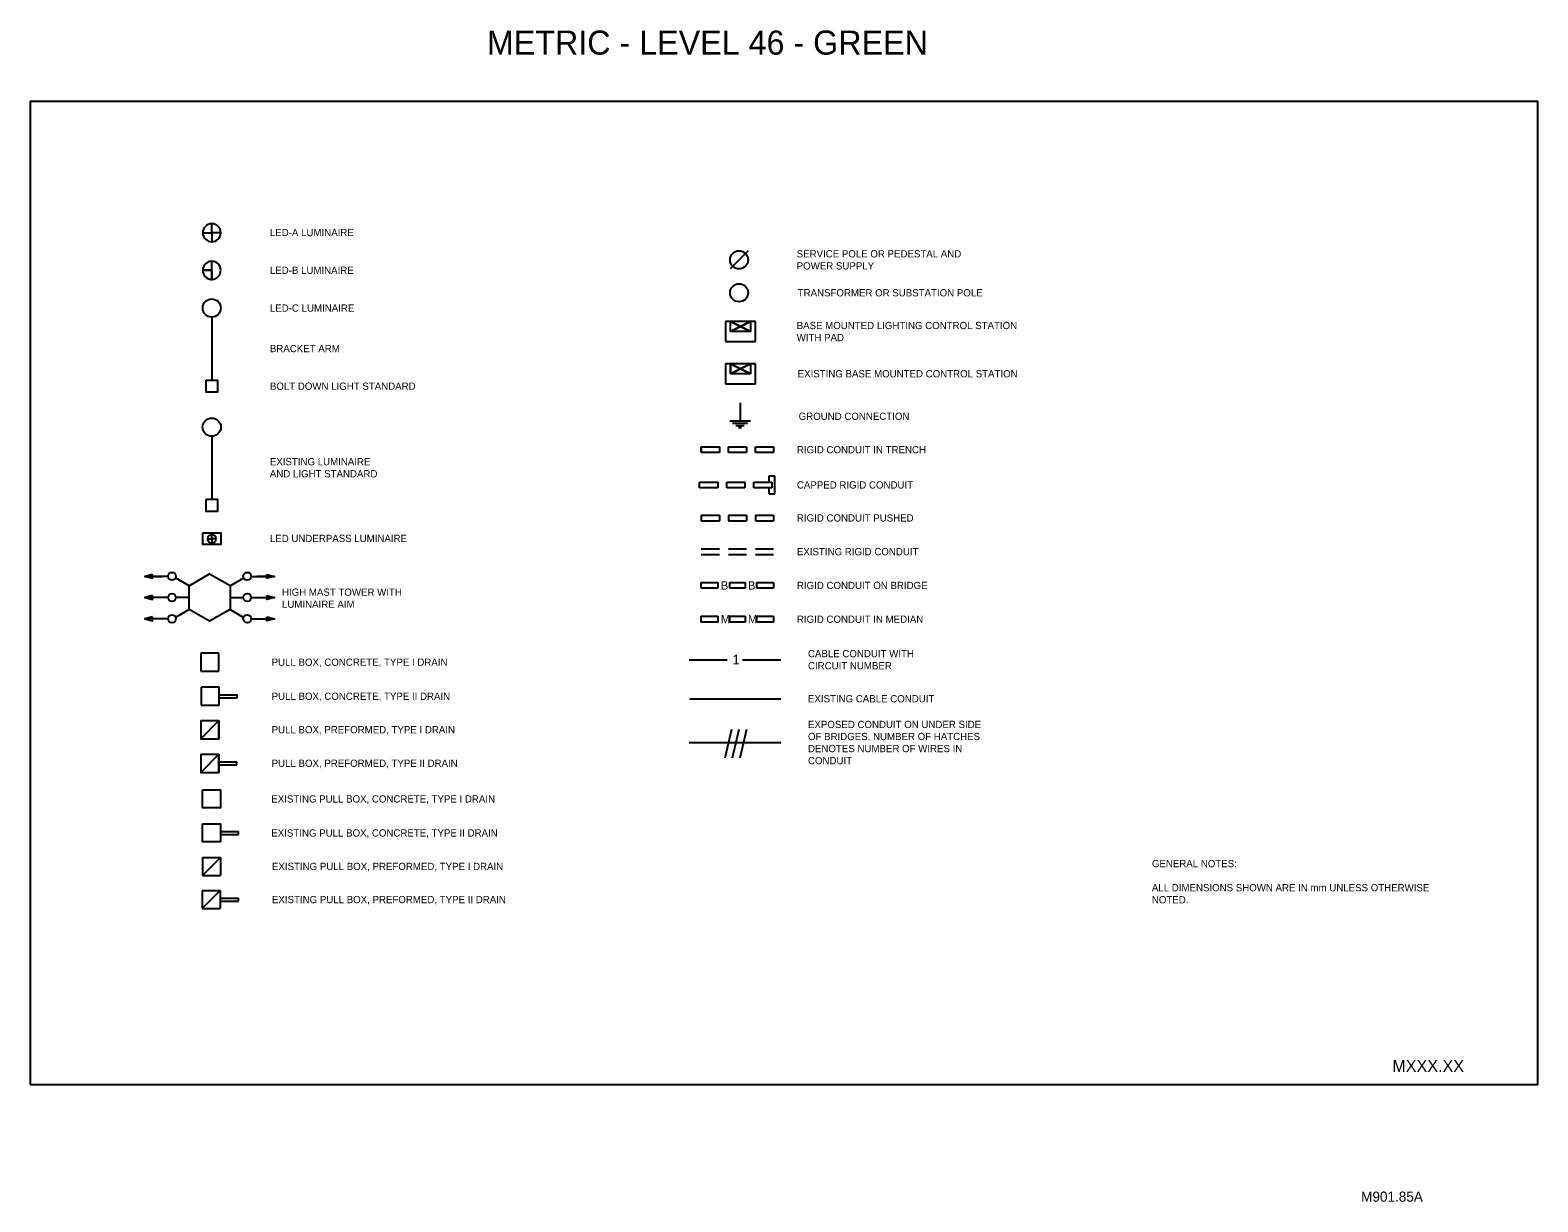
# Model space of a CAD drawing. Extents: x -439.1 to -407.9, y -460.5 to -436.2.
import ezdxf

# ---------------------------------------------------------------- set-up
doc = ezdxf.new("R2010")
doc.units = 0
for name, color, linetype in [('Draft_Named_Boundary', 7, 'Continuous'), ('Level 4', 7, 'Continuous'), ('Level 46', 7, 'Continuous'), ('Lighting_Signals-Conduit', 7, 'Continuous'), ('Lighting_Signals-Equipment', 7, 'Continuous')]:
    doc.layers.add(name, color=color, linetype=linetype)

msp = doc.modelspace()

# ---------------------------------------------------------------- linework, layer by layer
at = {"layer": 'Draft_Named_Boundary'}
msp.add_lwpolyline([(-439.109, -458.051), (-407.859, -458.051), (-407.859, -437.676), (-439.109, -437.676)], close=True, dxfattribs=at)
at = {"layer": 'Level 4'}
for p, q in [((-435.345, -440.396), (-435.345, -440.209)), ((-435.533, -440.396), (-435.345, -440.396)), ((-435.158, -440.396), (-435.345, -440.396)), ((-435.345, -440.396), (-435.345, -440.583)), ((-435.158, -440.396), (-435.158, -440.396)), ((-424.228, -440.77), (-424.602, -441.146)), ((-435.533, -441.175), (-435.345, -441.175)), ((-435.345, -441.175), (-435.345, -440.988)), ((-435.345, -441.175), (-435.345, -441.363)), ((-435.345, -442.145), (-435.345, -443.449)), ((-424.392, -443.923), (-424.392, -444.296)), ((-424.608, -444.296), (-424.176, -444.296)), ((-424.548, -444.344), (-424.242, -444.344)), ((-435.345, -444.616), (-435.345, -445.919)), ((-424.482, -444.392), (-424.308, -444.392)), ((-424.43, -444.435), (-424.363, -444.435)), ((-425.2, -444.833), (-425.2, -444.954)), ((-425.2, -444.954), (-425.2, -444.833)), ((-425.2, -444.954), (-425.2, -444.833)), ((-425.2, -444.833), (-424.824, -444.833)), ((-424.824, -444.954), (-425.2, -444.954)), ((-424.824, -444.833), (-424.824, -444.954)), ((-424.637, -444.954), (-424.637, -444.833)), ((-424.637, -444.833), (-424.262, -444.833)), ((-424.262, -444.954), (-424.637, -444.954)), ((-424.262, -444.833), (-424.262, -444.954)), ((-424.075, -444.954), (-424.075, -444.833)), ((-424.075, -444.833), (-423.7, -444.833)), ((-423.7, -444.954), (-424.075, -444.954)), ((-423.7, -444.833), (-423.7, -444.954)), ((-425.232, -445.684), (-425.232, -445.564)), ((-425.232, -445.564), (-424.857, -445.564)), ((-424.857, -445.564), (-424.857, -445.684)), ((-424.67, -445.684), (-424.67, -445.564)), ((-424.67, -445.564), (-424.294, -445.564)), ((-424.294, -445.564), (-424.294, -445.684)), ((-424.107, -445.684), (-424.107, -445.564)), ((-424.107, -445.564), (-423.733, -445.564)), ((-423.793, -445.437), (-423.673, -445.437)), ((-423.793, -445.564), (-423.793, -445.437)), ((-423.733, -445.564), (-423.733, -445.684)), ((-423.673, -445.811), (-423.673, -445.437)), ((-424.857, -445.684), (-425.232, -445.684)), ((-424.294, -445.684), (-424.67, -445.684)), ((-424.315, -445.684), (-424.295, -445.663)), ((-423.733, -445.684), (-424.107, -445.684)), ((-423.793, -445.811), (-423.793, -445.684)), ((-423.793, -445.811), (-423.673, -445.811)), ((-425.2, -446.248), (-425.2, -446.368)), ((-425.2, -446.248), (-424.824, -446.248)), ((-424.824, -446.248), (-424.824, -446.368)), ((-424.637, -446.248), (-424.637, -446.368)), ((-424.637, -446.248), (-424.262, -446.248)), ((-424.262, -446.248), (-424.262, -446.368)), ((-424.075, -446.248), (-424.075, -446.368)), ((-424.075, -446.248), (-423.7, -446.248)), ((-423.7, -446.248), (-423.7, -446.368)), ((-425.2, -446.368), (-424.824, -446.368)), ((-424.637, -446.368), (-424.262, -446.368)), ((-424.075, -446.368), (-423.7, -446.368)), ((-435.435, -446.739), (-435.345, -446.739)), ((-435.345, -446.739), (-435.345, -446.649)), ((-435.255, -446.739), (-435.345, -446.739)), ((-435.345, -446.739), (-435.345, -446.829)), ((-435.255, -446.739), (-435.255, -446.739)), ((-425.2, -446.947), (-424.824, -446.947)), ((-425.2, -447.067), (-424.824, -447.067)), ((-424.637, -446.947), (-424.262, -446.947)), ((-424.637, -447.067), (-424.262, -447.067)), ((-424.075, -446.947), (-423.7, -446.947)), ((-424.075, -447.067), (-423.7, -447.067)), ((-436.249, -447.519), (-436.733, -447.519)), ((-435.815, -447.712), (-436.097, -447.552)), ((-434.963, -447.712), (-434.682, -447.552)), ((-434.529, -447.519), (-434.046, -447.519)), ((-425.2, -447.767), (-425.2, -447.648)), ((-425.2, -447.648), (-424.855, -447.648)), ((-424.855, -447.767), (-425.2, -447.767)), ((-424.855, -447.648), (-424.855, -447.767)), ((-424.607, -447.767), (-424.607, -447.648)), ((-424.607, -447.648), (-424.292, -447.648)), ((-424.292, -447.767), (-424.607, -447.767)), ((-424.292, -447.648), (-424.292, -447.767)), ((-424.045, -447.767), (-424.045, -447.648)), ((-424.045, -447.648), (-423.7, -447.648)), ((-423.7, -447.767), (-424.045, -447.767)), ((-423.7, -447.648), (-423.7, -447.767)), ((-436.249, -447.957), (-436.733, -447.957)), ((-435.815, -447.958), (-436.08, -447.958)), ((-434.963, -447.958), (-434.698, -447.958)), ((-434.529, -447.957), (-434.046, -447.957)), ((-436.249, -448.399), (-436.733, -448.399)), ((-435.815, -448.203), (-436.093, -448.372)), ((-434.963, -448.203), (-434.686, -448.372)), ((-434.529, -448.399), (-434.046, -448.399)), ((-425.2, -448.466), (-425.2, -448.347)), ((-425.2, -448.347), (-424.855, -448.347)), ((-424.855, -448.347), (-424.855, -448.466)), ((-424.607, -448.466), (-424.607, -448.347)), ((-424.607, -448.347), (-424.292, -448.347)), ((-424.292, -448.347), (-424.292, -448.466)), ((-424.045, -448.466), (-424.045, -448.347)), ((-424.045, -448.347), (-423.7, -448.347)), ((-423.7, -448.347), (-423.7, -448.466)), ((-424.855, -448.466), (-425.2, -448.466)), ((-424.292, -448.466), (-424.607, -448.466)), ((-423.7, -448.466), (-424.045, -448.466)), ((-435.2, -449.111), (-435.574, -449.111)), ((-435.574, -449.111), (-435.574, -449.486)), ((-435.2, -449.486), (-435.2, -449.111)), ((-425.453, -449.246), (-424.659, -449.246)), ((-424.347, -449.246), (-423.553, -449.246)), ((-435.574, -449.486), (-435.2, -449.486)), ((-435.189, -449.817), (-435.565, -449.817)), ((-435.565, -449.817), (-435.565, -450.192)), ((-435.189, -450.192), (-435.189, -449.817)), ((-435.189, -449.974), (-434.815, -449.974)), ((-434.815, -450.034), (-434.815, -449.974)), ((-435.565, -450.192), (-435.189, -450.192)), ((-435.189, -450.034), (-434.815, -450.034)), ((-425.439, -450.055), (-423.553, -450.055)), ((-435.574, -450.51), (-435.574, -450.885)), ((-435.574, -450.51), (-435.2, -450.51)), ((-435.2, -450.51), (-435.574, -450.885)), ((-435.2, -450.51), (-435.2, -450.885)), ((-435.574, -450.885), (-435.2, -450.885)), ((-424.57, -450.694), (-424.711, -451.29)), ((-424.418, -450.694), (-424.559, -451.29)), ((-424.258, -450.694), (-424.399, -451.29)), ((-435.574, -451.206), (-435.574, -451.581)), ((-435.574, -451.206), (-435.198, -451.206)), ((-435.574, -451.581), (-435.198, -451.206)), ((-435.198, -451.206), (-435.198, -451.581)), ((-425.453, -450.963), (-423.553, -450.963)), ((-435.198, -451.363), (-434.824, -451.363)), ((-435.198, -451.423), (-434.824, -451.423)), ((-434.824, -451.423), (-434.824, -451.363)), ((-435.574, -451.581), (-435.198, -451.581)), ((-435.162, -452.808), (-434.788, -452.808)), ((-434.788, -452.868), (-434.788, -452.808)), ((-435.162, -452.868), (-434.788, -452.868)), ((-435.538, -453.344), (-435.538, -453.718)), ((-435.538, -453.344), (-435.164, -453.344)), ((-435.164, -453.344), (-435.538, -453.718)), ((-435.164, -453.344), (-435.164, -453.718)), ((-435.538, -453.718), (-435.164, -453.718)), ((-435.543, -454.03), (-435.543, -454.405)), ((-435.543, -454.03), (-435.168, -454.03)), ((-435.543, -454.405), (-435.168, -454.03)), ((-435.168, -454.03), (-435.168, -454.405)), ((-435.168, -454.188), (-434.794, -454.188)), ((-435.168, -454.248), (-434.794, -454.248)), ((-434.794, -454.248), (-434.794, -454.188)), ((-435.543, -454.405), (-435.168, -454.405))]:
    msp.add_line(p, q, dxfattribs=at)
for points in [[(-435.345, -441.175), (-435.533, -441.175), (-435.531, -441.204), (-435.525, -441.227), (-435.518, -441.247), (-435.505, -441.273), (-435.488, -441.296), (-435.469, -441.316), (-435.444, -441.335), (-435.414, -441.35), (-435.38, -441.359), (-435.345, -441.363)], [(-435.46, -443.449), (-435.229, -443.449), (-435.229, -443.704), (-435.46, -443.704)], [(-435.46, -445.919), (-435.229, -445.919), (-435.229, -446.173), (-435.46, -446.173)], [(-435.531, -446.619), (-435.158, -446.619), (-435.158, -446.857), (-435.531, -446.857)], [(-436.576, -447.48), (-436.733, -447.519), (-436.576, -447.559)], [(-434.963, -448.203), (-435.389, -448.449), (-435.815, -448.203), (-435.815, -447.712), (-435.389, -447.465), (-434.963, -447.711)], [(-434.202, -447.48), (-434.046, -447.519), (-434.202, -447.559)], [(-436.576, -447.918), (-436.733, -447.957), (-436.576, -447.997)], [(-434.202, -447.918), (-434.046, -447.957), (-434.202, -447.997)], [(-436.576, -448.36), (-436.733, -448.399), (-436.576, -448.438)], [(-434.202, -448.36), (-434.046, -448.399), (-434.202, -448.438)], [(-435.2, -450.51), (-435.574, -450.885), (-435.2, -450.885)], [(-435.198, -451.206), (-435.574, -451.581), (-435.198, -451.581)], [(-435.538, -451.944), (-435.164, -451.944), (-435.164, -452.319), (-435.538, -452.319)], [(-435.537, -452.65), (-435.162, -452.65), (-435.162, -453.025), (-435.537, -453.025)]]:
    msp.add_lwpolyline(points, close=True, dxfattribs=at)
for points in [[(-436.733, -447.519), (-436.537, -447.519), (-436.37, -447.519)], [(-434.046, -447.519), (-434.241, -447.519), (-434.408, -447.519)]]:
    msp.add_lwpolyline(points, dxfattribs=at)
for centre, radius in [((-424.415, -440.958), 0.187), ((-424.415, -441.641), 0.187), ((-435.345, -441.957), 0.188), ((-435.345, -444.426), 0.189), ((-436.169, -447.518), 0.0824), ((-434.61, -447.518), 0.0824), ((-436.169, -447.957), 0.0824), ((-434.61, -447.957), 0.0824), ((-436.169, -448.397), 0.0824), ((-434.61, -448.397), 0.0824)]:
    msp.add_circle(centre, radius, dxfattribs=at)
for centre, radius, start, end in [((-435.345, -440.396), 0.187, 89.9559, 179.9354), ((-435.345, -440.396), 0.187, 0.0646, 89.9559), ((-435.345, -440.396), 0.187, 179.9366, 270.0444), ((-435.345, -440.396), 0.187, 270.0444, 0.0635), ((-435.345, -441.175), 0.187, 89.9559, 179.9354), ((-435.345, -441.175), 0.187, 179.9366, 270.0444), ((-435.345, -441.176), 0.187, 208.5324, 0.2174), ((-435.345, -441.175), 0.187, 0.0646, 89.9559), ((-435.345, -446.739), 0.0896, 89.9559, 179.9354), ((-435.345, -446.739), 0.0896, 179.9366, 270.0444), ((-435.345, -446.739), 0.0896, 0.0646, 89.9559), ((-435.345, -446.739), 0.0896, 270.0444, 0.0635)]:
    msp.add_arc(centre, radius, start, end, dxfattribs=at)
at = {"layer": 'Lighting_Signals-Conduit'}
for p, q in [((-424.595, -443.319), (-424.595, -443.111)), ((-424.595, -443.111), (-424.179, -443.319)), ((-424.179, -443.111), (-424.595, -443.319)), ((-424.595, -443.319), (-424.179, -443.111)), ((-424.179, -443.319), (-424.595, -443.111)), ((-424.595, -443.111), (-424.595, -443.319)), ((-424.179, -443.111), (-424.179, -443.319))]:
    msp.add_line(p, q, dxfattribs=at)
at = {"layer": 'Lighting_Signals-Equipment'}
for p, q in [((-424.074, -442.236), (-424.699, -442.236)), ((-424.699, -442.236), (-424.699, -442.653)), ((-424.595, -442.444), (-424.595, -442.236)), ((-424.595, -442.236), (-424.179, -442.444)), ((-424.179, -442.236), (-424.595, -442.444)), ((-424.595, -442.236), (-424.179, -442.444)), ((-424.179, -442.236), (-424.595, -442.444)), ((-424.595, -442.444), (-424.595, -442.236)), ((-424.595, -442.236), (-424.179, -442.444)), ((-424.179, -442.236), (-424.595, -442.444)), ((-424.595, -442.444), (-424.595, -442.236)), ((-424.179, -442.444), (-424.595, -442.236)), ((-424.595, -442.444), (-424.179, -442.236)), ((-424.179, -442.444), (-424.595, -442.444)), ((-424.179, -442.236), (-424.179, -442.444)), ((-424.074, -442.653), (-424.074, -442.236)), ((-424.699, -442.653), (-424.074, -442.653)), ((-424.074, -443.111), (-424.699, -443.111)), ((-424.699, -443.111), (-424.699, -443.527)), ((-424.074, -443.527), (-424.074, -443.111)), ((-424.179, -443.319), (-424.595, -443.319)), ((-424.699, -443.527), (-424.074, -443.527))]:
    msp.add_line(p, q, dxfattribs=at)

# ---------------------------------------------------------------- texts
at = {"layer": 'Level 4'}
for s, height, p in [('LED-A LUMINAIRE', 0.15, (-434.14, -440.467)), ('SERVICE POLE OR PEDESTAL AND', 0.15, (-423.221, -440.908)), ('LED-B LUMINAIRE', 0.15, (-434.14, -441.25)), ('POWER SUPPLY', 0.15, (-423.221, -441.158)), ('TRANSFORMER OR SUBSTATION POLE', 0.15, (-423.2, -441.716)), ('LED-C LUMINAIRE', 0.15, (-434.14, -442.032)), ('WITH PAD', 0.15, (-423.221, -442.644)), ('BASE MOUNTED LIGHTING CONTROL STATION', 0.15, (-423.221, -442.394)), ('BRACKET ARM', 0.15, (-434.14, -442.872)), ('EXISTING BASE MOUNTED CONTROL STATION', 0.15, (-423.2, -443.394)), ('BOLT DOWN LIGHT STANDARD', 0.15, (-434.14, -443.652)), ('GROUND CONNECTION', 0.15, (-423.18, -444.276)), ('RIGID CONDUIT IN TRENCH', 0.15, (-423.216, -444.968)), ('EXISTING LUMINAIRE', 0.15, (-434.14, -445.217)), ('AND LIGHT STANDARD', 0.15, (-434.14, -445.467)), ('CAPPED RIGID CONDUIT', 0.15, (-423.216, -445.699)), ('RIGID CONDUIT PUSHED', 0.15, (-423.216, -446.383)), ('LED UNDERPASS LUMINAIRE', 0.15, (-434.14, -446.807)), ('EXISTING RIGID CONDUIT', 0.15, (-423.216, -447.082)), ('HIGH MAST TOWER WITH', 0.15, (-433.889, -447.921)), ('B', 0.171, (-424.792, -447.793)), ('B', 0.171, (-424.23, -447.793)), ('RIGID CONDUIT ON BRIDGE', 0.15, (-423.216, -447.782)), ('LUMINAIRE AIM', 0.15, (-433.889, -448.171)), ('M', 0.171, (-424.792, -448.492)), ('M', 0.171, (-424.23, -448.492)), ('RIGID CONDUIT IN MEDIAN', 0.15, (-423.216, -448.482)), ('CABLE CONDUIT WITH', 0.15, (-422.987, -449.196)), ('PULL BOX, CONCRETE, TYPE I DRAIN', 0.15, (-434.104, -449.373)), ('1', 0.2, (-424.552, -449.344)), ('CIRCUIT NUMBER', 0.15, (-422.987, -449.446)), ('PULL BOX, CONCRETE, TYPE II DRAIN', 0.15, (-434.104, -450.079)), ('EXISTING CABLE CONDUIT', 0.15, (-422.987, -450.13)), ('PULL BOX, PREFORMED, TYPE I DRAIN', 0.15, (-434.104, -450.772)), ('EXPOSED CONDUIT ON UNDER SIDE', 0.15, (-422.987, -450.663)), ('OF BRIDGES. NUMBER OF HATCHES', 0.15, (-422.987, -450.913)), ('DENOTES NUMBER OF WIRES IN', 0.15, (-422.987, -451.163)), ('PULL BOX, PREFORMED, TYPE II DRAIN', 0.15, (-434.104, -451.468)), ('CONDUIT', 0.15, (-422.987, -451.413)), ('EXISTING PULL BOX, CONCRETE, TYPE I DRAIN', 0.15, (-434.11, -452.207)), ('EXISTING PULL BOX, CONCRETE, TYPE II DRAIN', 0.15, (-434.11, -452.913)), ('EXISTING PULL BOX, PREFORMED, TYPE I DRAIN', 0.15, (-434.097, -453.606)), ('EXISTING PULL BOX, PREFORMED, TYPE II DRAIN', 0.15, (-434.097, -454.293))]:
    msp.add_text(s, height=height, dxfattribs=at).set_placement(p)
at = {"layer": 'Level 46'}
for s, height, p in [('METRIC - LEVEL 46 - GREEN', 0.5, (-429.642, -436.705)), ('GENERAL NOTES:', 0.15, (-415.859, -453.547)), ('ALL DIMENSIONS SHOWN ARE IN mm UNLESS OTHERWISE ', 0.15, (-415.859, -454.047)), ('NOTED.', 0.15, (-415.859, -454.297)), ('MXXX.XX', 0.25, (-410.875, -457.792)), ('M901.85A', 0.21, (-411.522, -460.481))]:
    msp.add_text(s, height=height, dxfattribs=at).set_placement(p)

doc.saveas('drawing.dxf')
